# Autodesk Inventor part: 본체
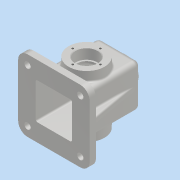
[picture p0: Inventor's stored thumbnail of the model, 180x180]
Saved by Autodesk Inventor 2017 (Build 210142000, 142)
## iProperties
Part Number: 본체
Material: 알루미늄 6061
Document SubType Name: Modeling
Designer: MRC
Density: 2.7 g/cm^3
Appearance: 알루미늄 - 평지
Mass: 753.624 g
Surface Area: 864.209 cm^2
Volume: 279.12 cm^3
Author: MRC
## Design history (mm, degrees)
sketch "스케치1"
  geometry: L1 (34, -52.5)-(-34, -52.5); L2 (-34, -52.5)-(-34, 52.5); L3 (-34, 52.5)-(34, 52.5); L4 (34, 52.5)-(34, -52.5); L5 (34, -52.5)-(-34, 52.5); L6 (-34, -52.5)-(34, 52.5); 1 further point
  constraints: 12 end point, 2 midpoint, 2 parallel, 1 horizontal, 1 perpendicular
  dimensions: "d0" = 68 distance of L2.end L3.end; "d1" = 105 distance of L1.end L2.end
extrude "돌출1" new body sketch "스케치1" stored distance "d2" = 68; taper "d3" = 0 deg
sketch "스케치2"
  geometry: L1 (5, -5)-(63, -5); L2 (63, -5)-(63, -63); L3 (63, -63)-(5, -63); L4 (5, -63)-(5, -5); L5 (5, -5)-(63, -63); L6 (63, -5)-(5, -63); 1 further point
  constraints: 12 end point, 2 midpoint, 2 parallel, 1 horizontal, 1 perpendicular
  dimensions: "d4" = 58 distance of L2.end L3.end; "d5" = 58 distance of L1.end L2.end
extrude "돌출2" cut sketch "스케치2" distance "d6" = 100; taper "d7" = 0 deg
sketch "스케치3"
  geometry: L1 (-34, -52.5)-(34, -52.5) reference; C1 r 28.5 at (0, -0.5); 1 further point
  constraints: 1 centre point, 1 vertical alignment
  dimensions: "d8" = 52 distance from line of C1.centre L1; "d9" = 57 diameter of C1
extrude "돌출3" join sketch "스케치3" distance "d10" = 15; taper "d11" = 0 deg
hole "구멍1" diameter "d14" = 30; stored, may be unused: countersink angle "d18" = 90 deg, drill point angle "d20" = 118 deg; dims "d12" = 10, "d13" = 10, "d15" = 6, "d16" = 35, "d17" = 17, "d19" = 8
sketch "스케치4"
  geometry: C1 r 17.5 at (0, 0) reference; 2 further points
  constraints: 1 vertical alignment
  dimensions: "d21" = 22 distance of point (0, 22) C1.centre
hole "구멍2" sketch "스케치4" at (0, 22) diameter "d22" = 3.242; stored, may be unused: countersink angle "d26" = 90 deg, drill point angle "d28" = 118 deg; dims "d23" = 8, "d24" = 35, "d25" = 17, "d27" = 10
fillet "모깎기1" dims "d29" = 8
node "작업 평면1"
sketch "스케치5"
  geometry: C1 r 20 at (-26, 34); 1 further point
  constraints: 1 centre point, 1 coincident
  dimensions: "d34" = 40 diameter of C1
extrude "돌출4" join sketch "스케치5" stored distance "d35" = 15; taper "d36" = 8 deg
hole "구멍3" diameter "d39" = 22.835; stored, may be unused: countersink angle "d43" = 90 deg, drill point angle "d45" = 118 deg; dims "d37" = 10, "d38" = 10, "d40" = 50, "d41" = 35, "d42" = 17, "d44" = 59.3
node "작업 평면2"
sketch "스케치6"
  geometry: L1 (0, 0)-(0, 52) reference; L2 (-60, 60)-(-8, 60) reference; L3 (-68, 52)-(-68, 0) reference; L4 (-8, -8)-(-60, -8) reference; L5 (23, 83)-(-91, 83); L6 (-91, 83)-(-91, -31); L7 (-91, -31)-(23, -31); L8 (23, -31)-(23, 83); L9 (23, 83)-(-91, -31); L10 (-91, 83)-(23, -31); A1 r 8 centre (-8, 52) between (0, 52) and (-8, 60) reference; A2 r 8 centre (-60, 52) between (-60, 60) and (-68, 52) reference; A3 r 8 centre (-60, 0) between (-68, 0) and (-60, -8) reference; A4 r 8 centre (-8, 0) between (-8, -8) and (0, 0) reference; 1 further point
  constraints: 12 end point, 2 midpoint, 2 parallel, 1 horizontal, 1 perpendicular
  dimensions: "d46" = 114 distance of L7.end L6.end; "d47" = 114 distance of L6.end L5.end
extrude "돌출5" join sketch "스케치6" distance "d48" = 10; taper "d49" = 0 deg
sketch "스케치7"
  geometry: 2 further points
  dimensions: "d50" = 42 horizontal distance of point (-76, -68) point (-34, -26); "d51" = 42 horizontal distance of point (-76, -68) point (-34, -26)
fillet "모깎기2" dims "d52" = 15
hole "구멍4" sketch "스케치7" diameter "d53" = 10; stored, may be unused: countersink angle "d57" = 90 deg, drill point angle "d59" = 0 deg; dims "d54" = 50, "d55" = 18, "d56" = 2, "d58" = 59.3
chamfer "모따기1" distance "d60" = 1; stored, may be unused: second distance "d61" = 2, angle "d62" = 45 deg
sketch "스케치8"
  geometry: L1 (-43.772, -12.848)-(-49, -42.5); L2 (-57, -42.5)-(-57, -52.5) reference; L3 (-51, -42.5)-(-33, -42.5) reference; 1 further point
  constraints: 2 end point, 1 point on line
  dimensions: "d63" = 10 deg angle of L2 L1; "d64" = 8 distance from line of L2 L1.end
feature "리브1" sketch "스케치8" dims "d65" = 1, "d66" = 10, "d67" = 0, "d68" = 0, "d69" = 1, "d70" = 1
fillet "모깎기3" dims "d71" = 3
fillet "모깎기4" dims "d72" = 0.3
fillet "모깎기5" dims "d73" = 3
sketch "스케치9"
  geometry: L1 (-34, 44.5)-(-34, -39.5) reference; L2 (-20, 62.5)-(20, 62.5) reference; 2 further points
  constraints: 1 other
  dimensions: "d74" = 34 distance from line of L1 point (0, 37.5); "d75" = 25 distance from line of L2 point (0, 37.5)
feature "엠보싱1" sketch "스케치9" dims "d0" = 68, "d1" = 105, "d8" = 52, "d9" = 57, "d76" = 0.5, "d77" = 0
node "솔리드1"
pattern_circular "원형 패턴1" dims angle "d31" = 360 deg
mirror "미러1"
mirror "미러2"
mirror "미러3"
mirror "미러4"
other parameters: "d33" = -115
